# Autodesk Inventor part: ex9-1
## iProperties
Author: Administrator
Created: 2001-09
Part Number: ex9-1
Document SubType Name: Sheet Metal
Designer: Administrator
Control State: 0
Master: False
Checked Out: False
PropertySet Name: Design Tracking Control
Length Units: 11272
Angle Units: 11279
Time Units: 11290
Mass Units: 11286
Shininess: 3
Angle Display Precision: 2
Document Length Units: 11272
Document Angle Units: 11286
Document Time Units: 11279
Document Mass Units: 11290
Document Length Units Precision: 3
Document Angle Units Precision: 2
Compacted: False
PropertySet Name: _Private Model Information
Density: 0.0
Volumn: 0.0
Area: 0.0
PropertySet Name: Model Information
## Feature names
1. Plate1
2. Bend1
